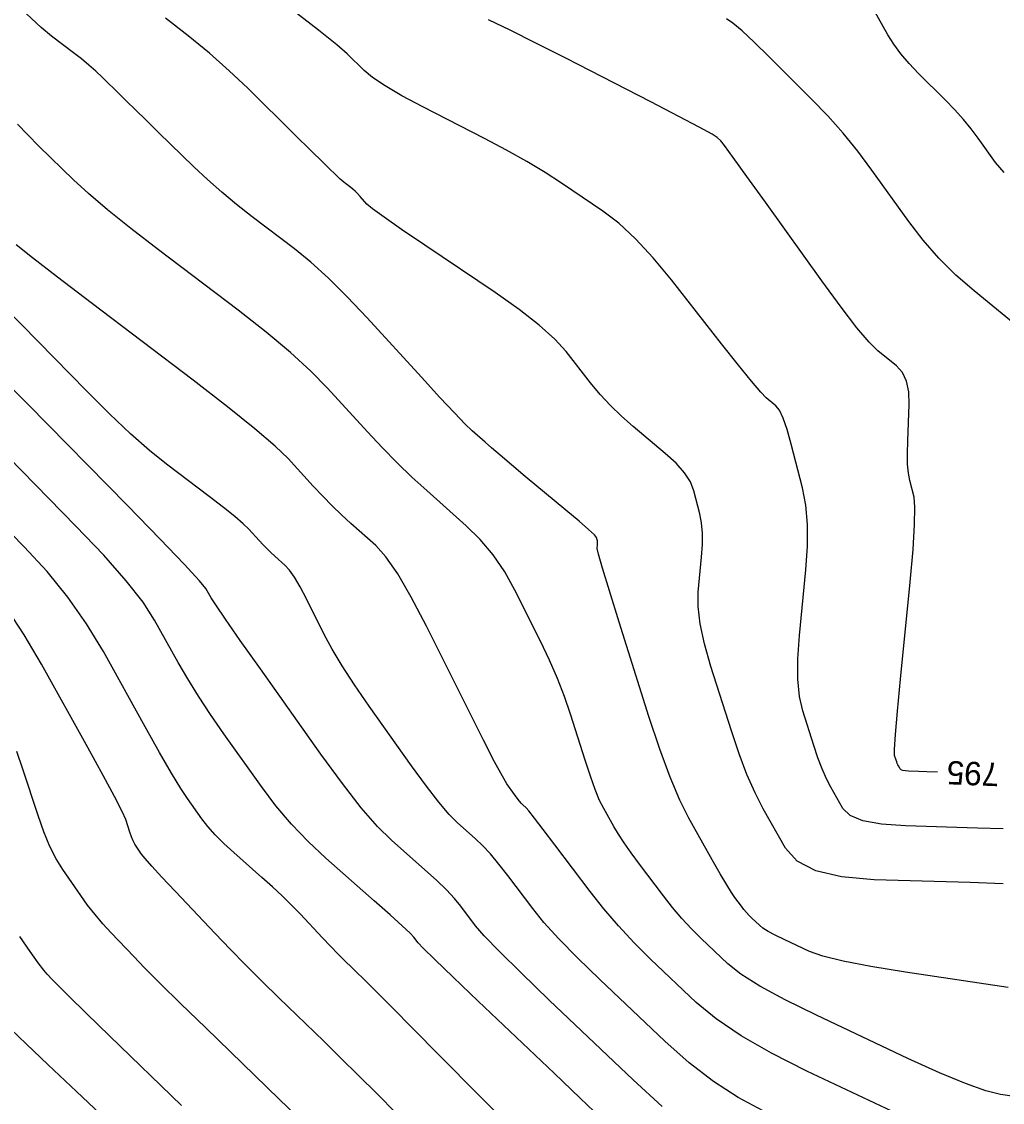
# Model space of a CAD drawing. Extents: x 2082232 to 2083549, y 592624 to 593832.
# Drawn here: x 2082350.27 to 2082379.59, y 593278.8 to 593311.11 of the extents above; entities that cross this region are included whole.
import ezdxf

# ---------------------------------------------------------------- set-up
doc = ezdxf.new("R2010")
doc.units = 0
doc.layers.add('DT_X_Contour_Major', color=7, linetype='Continuous')
doc.layers.add('DT_X_Contour_Minor', color=7, linetype='Continuous')

msp = doc.modelspace()

# ---------------------------------------------------------------- linework, layer by layer
at = {"layer": 'DT_X_Contour_Major'}
for points in [[(2082377.643, 593288.672), (2082377.33, 593288.684), (2082377.076, 593288.694), (2082376.784, 593288.703), (2082376.685, 593288.709), (2082376.61, 593288.724), (2082376.557, 593288.745), (2082376.528, 593288.774), (2082376.479, 593288.86), (2082376.461, 593288.894), (2082376.444, 593288.934), (2082376.426, 593288.98), (2082376.409, 593289.03), (2082376.365, 593289.171), (2082376.364, 593289.353), (2082376.393, 593289.794), (2082376.453, 593290.493), (2082376.544, 593291.451), (2082376.827, 593294.35), (2082376.914, 593295.324), (2082376.963, 593296.073), (2082376.973, 593296.598), (2082376.944, 593296.897), (2082376.817, 593297.394), (2082376.777, 593297.608), (2082376.753, 593297.877), (2082376.746, 593298.201), (2082376.755, 593298.58), (2082376.799, 593299.664), (2082376.788, 593300.041), (2082376.721, 593300.358), (2082376.597, 593300.616), (2082376.418, 593300.815), (2082375.866, 593301.266), (2082375.605, 593301.524), (2082375.239, 593301.96), (2082374.767, 593302.573), (2082374.189, 593303.364), (2082372.506, 593305.709), (2082371.949, 593306.483), (2082371.54, 593307.047), (2082371.279, 593307.402), (2082371.166, 593307.546), (2082371.062, 593307.65), (2082370.908, 593307.745), (2082370.526, 593307.953), (2082369.916, 593308.274), (2082369.077, 593308.708), (2082366.534, 593310.015), (2082365.642, 593310.469), (2082364.873, 593310.851), (2082364.226, 593311.161)], [(2082376.791, 593278.299), (2082373.744, 593279.736), (2082372.681, 593280.268), (2082371.775, 593280.787), (2082371.027, 593281.294), (2082370.436, 593281.786), (2082369.072, 593283.083), (2082368.575, 593283.574), (2082368.108, 593284.074), (2082367.67, 593284.583), (2082367.262, 593285.102), (2082366.212, 593286.497), (2082365.863, 593286.959), (2082365.603, 593287.299), (2082365.432, 593287.515), (2082365.35, 593287.609), (2082365.251, 593287.696), (2082365.208, 593287.74), (2082365.153, 593287.806), (2082365.085, 593287.894), (2082365.006, 593288.003), (2082364.778, 593288.325), (2082364.643, 593288.55), (2082364.41, 593288.985), (2082364.078, 593289.629), (2082363.648, 593290.482), (2082362.37, 593293.036), (2082361.916, 593293.905), (2082361.512, 593294.597), (2082361.158, 593295.111), (2082360.854, 593295.448), (2082360.11, 593296.109), (2082359.83, 593296.365), (2082359.55, 593296.636), (2082359.27, 593296.921), (2082358.988, 593297.222), (2082358.238, 593298.044), (2082357.849, 593298.422), (2082357.245, 593298.939), (2082356.427, 593299.596), (2082355.394, 593300.392), (2082352.353, 593302.7), (2082351.344, 593303.47), (2082350.595, 593304.048), (2082350.106, 593304.434)], [(2082361.461, 593278.479), (2082360.894, 593279.052), (2082360.345, 593279.601), (2082359.813, 593280.126), (2082359.3, 593280.627), (2082357.956, 593281.93), (2082357.459, 593282.416), (2082356.977, 593282.899), (2082356.508, 593283.377), (2082356.054, 593283.851), (2082354.862, 593285.111), (2082354.464, 593285.535), (2082354.164, 593285.86), (2082353.961, 593286.087), (2082353.857, 593286.216), (2082353.71, 593286.429), (2082353.655, 593286.517), (2082353.603, 593286.621), (2082353.553, 593286.741), (2082353.505, 593286.876), (2082353.381, 593287.259), (2082353.275, 593287.501), (2082353.052, 593287.94), (2082352.71, 593288.577), (2082352.251, 593289.41), (2082350.868, 593291.896), (2082350.35, 593292.776), (2082349.835, 593293.553)]]:
    msp.add_lwpolyline(points, dxfattribs=at)
at = {"layer": 'DT_X_Contour_Minor'}
for points in [[(2082379.613, 593286.977), (2082378.837, 593287.001), (2082376.691, 593287.067), (2082375.97, 593287.118), (2082375.416, 593287.222), (2082375.031, 593287.378), (2082374.814, 593287.588), (2082374.459, 593288.219), (2082374.327, 593288.474), (2082374.197, 593288.767), (2082374.071, 593289.098), (2082373.947, 593289.467), (2082373.62, 593290.501), (2082373.522, 593290.932), (2082373.473, 593291.452), (2082373.472, 593292.059), (2082373.52, 593292.754), (2082373.712, 593294.725), (2082373.76, 593295.432), (2082373.758, 593296.077), (2082373.707, 593296.658), (2082373.607, 593297.177), (2082373.275, 593298.475), (2082373.152, 593298.913), (2082373.034, 593299.25), (2082372.921, 593299.489), (2082372.812, 593299.628), (2082372.527, 593299.866), (2082372.363, 593300.033), (2082372.086, 593300.357), (2082371.695, 593300.838), (2082371.191, 593301.476), (2082369.696, 593303.386), (2082369.147, 593304.052), (2082368.622, 593304.617), (2082368.122, 593305.081), (2082367.646, 593305.444), (2082366.409, 593306.279), (2082365.916, 593306.597), (2082365.368, 593306.926), (2082364.763, 593307.265), (2082364.102, 593307.614), (2082362.265, 593308.56), (2082361.638, 593308.894), (2082361.136, 593309.186), (2082360.758, 593309.436), (2082360.506, 593309.645), (2082359.998, 593310.145), (2082359.688, 593310.416), (2082359.14, 593310.855), (2082358.354, 593311.462)], [(2082379.638, 593306.595), (2082379.384, 593306.901), (2082378.863, 593307.628), (2082378.654, 593307.903), (2082378.42, 593308.185), (2082378.16, 593308.473), (2082377.875, 593308.768), (2082377.079, 593309.563), (2082376.798, 593309.858), (2082376.552, 593310.149), (2082376.34, 593310.435), (2082376.164, 593310.716), (2082375.739, 593311.46)], [(2082379.755, 593282.232), (2082376.69, 593282.695), (2082375.649, 593282.863), (2082374.824, 593283.022), (2082374.214, 593283.171), (2082373.82, 593283.311), (2082373.059, 593283.67), (2082372.798, 593283.798), (2082372.589, 593283.912), (2082372.43, 593284.012), (2082372.322, 593284.097), (2082372.101, 593284.307), (2082372.02, 593284.388), (2082371.94, 593284.474), (2082371.862, 593284.566), (2082371.787, 593284.662), (2082371.588, 593284.927), (2082371.49, 593285.072), (2082371.345, 593285.308), (2082371.153, 593285.636), (2082370.914, 593286.056), (2082370.215, 593287.296), (2082369.943, 593287.836), (2082369.654, 593288.523), (2082369.347, 593289.358), (2082369.022, 593290.341), (2082368.131, 593293.161), (2082367.839, 593294.091), (2082367.632, 593294.768), (2082367.509, 593295.191), (2082367.471, 593295.361), (2082367.482, 593295.475), (2082367.485, 593295.516), (2082367.485, 593295.553), (2082367.482, 593295.587), (2082367.476, 593295.617), (2082367.457, 593295.692), (2082367.394, 593295.764), (2082367.219, 593295.924), (2082366.933, 593296.171), (2082366.536, 593296.506), (2082365.326, 593297.515), (2082364.911, 593297.863), (2082364.573, 593298.148), (2082364.311, 593298.372), (2082364.126, 593298.533), (2082363.735, 593298.881), (2082363.531, 593299.078), (2082363.211, 593299.41), (2082362.774, 593299.876), (2082362.222, 593300.476), (2082360.596, 593302.257), (2082360.003, 593302.886), (2082359.444, 593303.439), (2082358.919, 593303.914), (2082358.427, 593304.313), (2082357.161, 593305.274), (2082356.696, 593305.638), (2082356.251, 593306.008), (2082355.825, 593306.385), (2082355.419, 593306.768), (2082354.362, 593307.799), (2082353.992, 593308.16), (2082353.673, 593308.472), (2082353.406, 593308.733), (2082353.192, 593308.944), (2082352.688, 593309.44), (2082352.492, 593309.626), (2082352.282, 593309.811), (2082352.057, 593309.996), (2082351.817, 593310.181), (2082351.16, 593310.674), (2082350.851, 593310.934), (2082350.418, 593311.342)], [(2082379.604, 593285.335), (2082378.622, 593285.369), (2082375.751, 593285.456), (2082374.777, 593285.54), (2082374.011, 593285.726), (2082373.452, 593286.013), (2082373.1, 593286.403), (2082372.438, 593287.578), (2082372.192, 593288.054), (2082371.951, 593288.6), (2082371.715, 593289.217), (2082371.484, 593289.904), (2082370.876, 593291.831), (2082370.681, 593292.512), (2082370.552, 593293.11), (2082370.491, 593293.625), (2082370.495, 593294.058), (2082370.597, 593295.1), (2082370.623, 593295.474), (2082370.622, 593295.815), (2082370.595, 593296.123), (2082370.542, 593296.397), (2082370.366, 593297.084), (2082370.263, 593297.347), (2082370.086, 593297.621), (2082369.836, 593297.906), (2082369.511, 593298.202), (2082368.548, 593299.006), (2082368.197, 593299.314), (2082367.869, 593299.634), (2082367.562, 593299.966), (2082367.276, 593300.311), (2082366.544, 593301.246), (2082366.206, 593301.619), (2082365.739, 593302.037), (2082365.145, 593302.5), (2082364.422, 593303.008), (2082362.325, 593304.423), (2082361.627, 593304.898), (2082361.106, 593305.262), (2082360.762, 593305.515), (2082360.594, 593305.656), (2082360.385, 593305.886), (2082360.309, 593305.967), (2082360.238, 593306.037), (2082360.172, 593306.097), (2082360.111, 593306.147), (2082359.955, 593306.265), (2082359.898, 593306.31), (2082359.843, 593306.355), (2082359.791, 593306.401), (2082359.741, 593306.449), (2082359.611, 593306.575), (2082359.502, 593306.683), (2082359.271, 593306.909), (2082358.92, 593307.254), (2082358.448, 593307.719), (2082357.029, 593309.117), (2082356.476, 593309.641), (2082355.882, 593310.164), (2082355.248, 593310.687), (2082354.573, 593311.209)], [(2082380.246, 593301.83), (2082378.741, 593303.059), (2082378.196, 593303.534), (2082377.688, 593304.038), (2082377.219, 593304.571), (2082376.786, 593305.132), (2082375.684, 593306.668), (2082375.262, 593307.232), (2082374.823, 593307.773), (2082374.367, 593308.29), (2082373.893, 593308.783), (2082372.606, 593310.068), (2082372.165, 593310.499), (2082371.806, 593310.83), (2082371.529, 593311.06), (2082371.335, 593311.189)], [(2082380.486, 593278.896), (2082379.532, 593279.04), (2082379.091, 593279.148), (2082378.483, 593279.363), (2082377.707, 593279.686), (2082376.764, 593280.117), (2082374.027, 593281.408), (2082373.091, 593281.867), (2082372.338, 593282.276), (2082371.767, 593282.634), (2082371.379, 593282.942), (2082370.587, 593283.695), (2082370.293, 593283.987), (2082370.007, 593284.297), (2082369.728, 593284.625), (2082369.456, 593284.973), (2082368.741, 593285.923), (2082368.492, 593286.26), (2082368.282, 593286.559), (2082368.109, 593286.82), (2082367.975, 593287.043), (2082367.669, 593287.587), (2082367.548, 593287.83), (2082367.415, 593288.151), (2082367.27, 593288.551), (2082367.112, 593289.028), (2082366.677, 593290.407), (2082366.498, 593290.931), (2082366.289, 593291.468), (2082366.049, 593292.02), (2082365.778, 593292.585), (2082365.014, 593294.111), (2082364.709, 593294.66), (2082364.364, 593295.165), (2082363.981, 593295.625), (2082363.559, 593296.04), (2082362.38, 593297.088), (2082361.938, 593297.493), (2082361.495, 593297.921), (2082361.051, 593298.373), (2082360.605, 593298.849), (2082359.417, 593300.151), (2082358.915, 593300.662), (2082358.303, 593301.221), (2082357.579, 593301.827), (2082356.743, 593302.479), (2082354.367, 593304.283), (2082353.54, 593304.922), (2082352.839, 593305.485), (2082352.265, 593305.972), (2082351.819, 593306.383), (2082350.797, 593307.38), (2082350.443, 593307.732), (2082350.147, 593308.043)], [(2082372.433, 593278.549), (2082371.691, 593278.942), (2082370.954, 593279.42), (2082370.222, 593279.983), (2082369.494, 593280.631), (2082367.557, 593282.471), (2082366.887, 593283.121), (2082366.329, 593283.691), (2082365.883, 593284.182), (2082365.548, 593284.592), (2082364.805, 593285.579), (2082364.536, 593285.926), (2082364.284, 593286.226), (2082364.051, 593286.478), (2082363.837, 593286.683), (2082363.288, 593287.166), (2082363.049, 593287.408), (2082362.742, 593287.772), (2082362.369, 593288.258), (2082361.928, 593288.866), (2082360.663, 593290.648), (2082360.223, 593291.283), (2082359.852, 593291.851), (2082359.549, 593292.351), (2082359.315, 593292.784), (2082358.782, 593293.849), (2082358.593, 593294.212), (2082358.424, 593294.5), (2082358.276, 593294.714), (2082358.149, 593294.855), (2082357.839, 593295.131), (2082357.723, 593295.238), (2082357.606, 593295.35), (2082357.489, 593295.47), (2082357.371, 593295.595), (2082357.058, 593295.938), (2082356.896, 593296.095), (2082356.644, 593296.311), (2082356.303, 593296.585), (2082355.872, 593296.917), (2082354.604, 593297.88), (2082354.098, 593298.288), (2082353.529, 593298.79), (2082352.898, 593299.386), (2082352.206, 593300.076), (2082350.276, 593302.041), (2082349.629, 593302.691)], [(2082369.417, 593278.673), (2082368.551, 593279.476), (2082366.043, 593281.859), (2082365.199, 593282.669), (2082364.55, 593283.309), (2082364.095, 593283.78), (2082363.835, 593284.082), (2082363.398, 593284.662), (2082363.209, 593284.893), (2082362.966, 593285.153), (2082362.671, 593285.44), (2082362.323, 593285.756), (2082361.324, 593286.636), (2082360.912, 593287.044), (2082360.424, 593287.609), (2082359.859, 593288.33), (2082359.218, 593289.208), (2082357.409, 593291.759), (2082356.808, 593292.609), (2082356.362, 593293.246), (2082356.071, 593293.67), (2082355.935, 593293.882), (2082355.779, 593294.162), (2082355.588, 593294.396), (2082355.133, 593294.888), (2082354.415, 593295.637), (2082353.432, 593296.643), (2082350.46, 593299.67), (2082349.458, 593300.673)], [(2082367.593, 593278.326), (2082366.965, 593278.93), (2082366.188, 593279.67), (2082363.919, 593281.826), (2082363.169, 593282.541), (2082362.619, 593283.071), (2082362.27, 593283.414), (2082362.121, 593283.572), (2082361.992, 593283.744), (2082361.881, 593283.86), (2082361.648, 593284.08), (2082361.29, 593284.403), (2082360.809, 593284.83), (2082359.361, 593286.105), (2082358.833, 593286.598), (2082358.337, 593287.119), (2082357.871, 593287.668), (2082357.436, 593288.245), (2082356.317, 593289.821), (2082355.917, 593290.398), (2082355.556, 593290.946), (2082355.234, 593291.464), (2082354.95, 593291.953), (2082354.246, 593293.219), (2082353.901, 593293.751), (2082353.394, 593294.396), (2082352.724, 593295.155), (2082351.892, 593296.028), (2082349.458, 593298.507)], [(2082365.118, 593277.816), (2082362.764, 593280.206), (2082361.969, 593281.012), (2082361.348, 593281.64), (2082360.902, 593282.088), (2082360.63, 593282.356), (2082360.137, 593282.834), (2082359.944, 593283.024), (2082359.734, 593283.235), (2082359.508, 593283.469), (2082359.264, 593283.724), (2082358.593, 593284.433), (2082358.334, 593284.701), (2082358.057, 593284.972), (2082357.765, 593285.246), (2082357.455, 593285.524), (2082356.609, 593286.27), (2082356.311, 593286.543), (2082356.053, 593286.802), (2082355.834, 593287.049), (2082355.654, 593287.281), (2082355.226, 593287.884), (2082355.027, 593288.187), (2082354.751, 593288.645), (2082354.397, 593289.258), (2082353.966, 593290.025), (2082352.714, 593292.276), (2082352.214, 593293.105), (2082351.654, 593293.904), (2082351.033, 593294.673), (2082350.352, 593295.412), (2082348.456, 593297.343)], [(2082358.725, 593278.165), (2082357.971, 593278.897), (2082355.775, 593281.025), (2082355.023, 593281.757), (2082354.414, 593282.356), (2082353.947, 593282.823), (2082353.622, 593283.157), (2082352.946, 593283.871), (2082352.699, 593284.142), (2082352.465, 593284.418), (2082352.245, 593284.699), (2082352.038, 593284.986), (2082351.503, 593285.758), (2082351.306, 593286.077), (2082351.117, 593286.453), (2082350.936, 593286.887), (2082350.763, 593287.378), (2082350.312, 593288.765), (2082350.125, 593289.29)], [(2082355.049, 593278.712), (2082352.912, 593280.783), (2082352.203, 593281.47), (2082351.68, 593281.979), (2082351.342, 593282.31), (2082351.19, 593282.462), (2082351.03, 593282.631), (2082350.934, 593282.749), (2082350.767, 593282.976), (2082350.529, 593283.311), (2082350.219, 593283.756)], [(2082354.429, 593276.743), (2082351.91, 593279.122), (2082351.062, 593279.924), (2082350.409, 593280.548), (2082349.95, 593280.994)]]:
    msp.add_lwpolyline(points, dxfattribs=at)

# ---------------------------------------------------------------- texts
at = {"layer": 'DT_X_Contour_Major'}
msp.add_text('795', height=0.7, rotation=177.7305, dxfattribs=at).set_placement((2082379.502, 593288.949))

doc.saveas('drawing.dxf')
